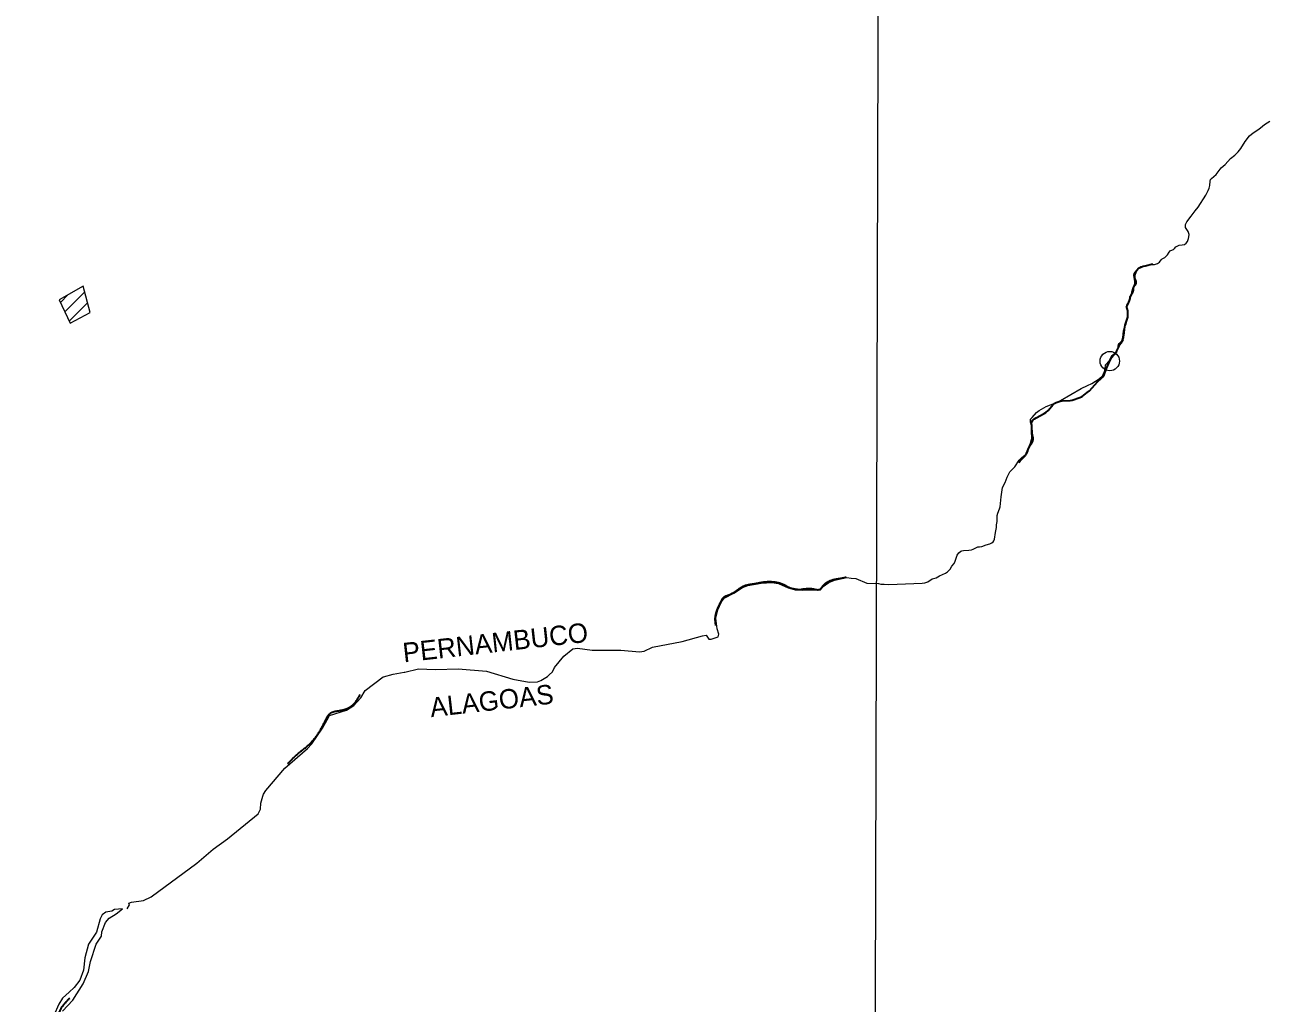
# Model space of a CAD drawing. Extents: x 553962 to 842807, y 8883888 to 9032388.
# Drawn here: x 582130 to 587242, y 8915863 to 8919892 of the extents above; entities that cross this region are included whole.
import ezdxf
from ezdxf.enums import TextEntityAlignment as Align

# ---------------------------------------------------------------- set-up
doc = ezdxf.new("R2010")
doc.units = 0
doc.header["$LTSCALE"] = 160
doc.header["$PDMODE"] = 32
doc.header["$PDSIZE"] = 80
doc.linetypes.add('LONG_DASH_SHORT_DASH', pattern=[9.9, 6, -1.2, 1.5, -1.2])
doc.layers.add('6', color=7, linetype='Continuous', lineweight=13)

msp = doc.modelspace()

# ---------------------------------------------------------------- linework, layer by layer
at = {"layer": '6'}
for p, q in [((582276.5, 8918748), (582308.9, 8918780.4)), ((582294.7, 8918709.6), (582376.4, 8918791.3)), ((582312.9, 8918671.2), (582388.6, 8918746.9))]:
    msp.add_line(p, q, dxfattribs=at)
at = {"layer": '6', "linetype": 'LONG_DASH_SHORT_DASH', "lineweight": 35}
msp.add_line((585799, 8917597.9), (585799.3, 8917597.8), dxfattribs=at)
at = {"layer": '6'}
for points in [[(585656.3, 8924738.8), (585614.8, 8909969.8), (585579.9, 8898162.7)], [(586916.9, 8918999.4), (586921.8, 8919011.7), (586923.2, 8919017.8), (586923.8, 8919027.8), (586919.9, 8919040.7), (586909.9, 8919057.1), (586909, 8919064.2), (586909.4, 8919069.7), (586914.4, 8919080.4), (586932.4, 8919104.2), (586949.8, 8919125.1), (586961.5, 8919140.2), (586992.8, 8919190.2), (587002.7, 8919209.4), (587006.2, 8919218.4), (587008.9, 8919230.4), (587010.4, 8919247.4), (587012.9, 8919254.6), (587016, 8919258.6), (587035, 8919274.8), (587055.6, 8919302.4), (587072, 8919316.4), (587094, 8919340.4), (587112.3, 8919355.2), (587126.1, 8919368.8), (587137.1, 8919382), (587155.1, 8919411), (587172.6, 8919433.8), (587187.4, 8919446.2), (587211.4, 8919462), (587226.2, 8919474.8), (587234.8, 8919481.4), (587256, 8919495)], [(586679.6, 8918760.5), (586680.3, 8918772.5), (586692.5, 8918786.5), (586696.8, 8918798.9), (586696.9, 8918809.3), (586697.7, 8918812.7), (586699.3, 8918815.3), (586704.2, 8918820.1), (586707.7, 8918826.9), (586707.4, 8918834.5), (586702.6, 8918847.7), (586701.8, 8918857.5), (586703.1, 8918864.1), (586709.7, 8918881.3), (586721, 8918893.5), (586725.9, 8918895.7), (586766.1, 8918904.9), (586782.2, 8918905.1), (586794.3, 8918909.1), (586801.8, 8918914.7), (586808.8, 8918923.3), (586813, 8918927.3), (586824.3, 8918933.9), (586830.1, 8918938.5), (586834.8, 8918944.1), (586841.9, 8918955.9), (586845.8, 8918960.3), (586848.8, 8918962.4), (586859.7, 8918966.8), (586863.7, 8918970.4), (586869.3, 8918977.4), (586877.2, 8918981.7), (586883.6, 8918984.1), (586895.7, 8918985.2), (586905.7, 8918987.4), (586911.9, 8918992.7), (586916.9, 8918999.4)], [(586136.8, 8917879.9), (586143.9, 8917898.3), (586146.5, 8917907.1), (586150.7, 8917947.5), (586156.3, 8917986.5), (586166.2, 8918006.3), (586175.4, 8918028.7), (586186.6, 8918050.1), (586197.8, 8918063.5), (586206.1, 8918071.9), (586225, 8918098.7), (586234.8, 8918109.9), (586249.5, 8918120.5), (586256.8, 8918127.7), (586261.3, 8918135.7), (586262.8, 8918149.5), (586276.3, 8918165.5), (586281.8, 8918176.7), (586282.8, 8918182.3), (586282.8, 8918191.1), (586279.2, 8918209.5), (586279.1, 8918219.3), (586275.1, 8918241.3), (586270.8, 8918255.1), (586270.6, 8918261.3), (586271.5, 8918267.7), (586278.2, 8918274.1), (586295.8, 8918294.9), (586307.4, 8918303.7), (586335.1, 8918320.1), (586377.8, 8918336.7), (586395.1, 8918344.9), (586480.1, 8918393.5), (586505.7, 8918406.7), (586524.1, 8918414.9), (586554, 8918433.1), (586568.4, 8918447.3), (586570.6, 8918451.1), (586575.7, 8918463.9), (586578.3, 8918475.3), (586579.7, 8918491.9), (586595.5, 8918507.3), (586602.8, 8918522.3), (586607.5, 8918529.5), (586619.7, 8918540.1), (586627.3, 8918548.9), (586630.1, 8918555.5), (586632.3, 8918569.5), (586634.1, 8918575.1), (586636.7, 8918579.5), (586645.9, 8918589.1), (586648.8, 8918594.9), (586650.6, 8918604.3), (586653.5, 8918631.7), (586658.1, 8918644.7), (586665.3, 8918659.3), (586672.6, 8918692.7), (586672.6, 8918710.3), (586671.1, 8918715.7), (586665.9, 8918726.3), (586666, 8918731.5), (586668, 8918736.7), (586678.5, 8918755.1), (586678.5, 8918755.1), (586679.6, 8918760.5)], [(585824.4, 8917592.5), (585835.6, 8917593.5), (585848.5, 8917598.3), (585866.6, 8917609.5), (585883, 8917614.7), (585896.8, 8917622.9), (585921, 8917633.3), (585928.7, 8917638.5), (585940.3, 8917649.7), (585947.5, 8917662.7), (585957.1, 8917673.5), (585961.2, 8917682.5), (585965.9, 8917699.7), (585968.9, 8917706.9), (585976, 8917717.1), (585984.1, 8917723.9), (585988.6, 8917725.7), (585994.5, 8917727.1), (586017.6, 8917728.5), (586028.1, 8917729.9), (586035.3, 8917731.9), (586054, 8917741.3), (586060.6, 8917742.5), (586070, 8917742.7), (586088.9, 8917750.3), (586104.1, 8917754.3), (586112.5, 8917757.7), (586118, 8917762.1), (586120.7, 8917766.5), (586122.9, 8917773.1), (586126.9, 8917800.7), (586130.7, 8917821.1), (586131.4, 8917832.3), (586133.7, 8917846.3), (586134.3, 8917870.5), (586136.8, 8917879.9)], [(585406.5, 8917564.6), (585417.5, 8917578), (585441.3, 8917595.2), (585463.8, 8917604.5), (585514.8, 8917615.6), (585533.1, 8917613.4)], [(585533.1, 8917613.4), (585551.5, 8917611.2), (585597.6, 8917591.8)], [(584946, 8917362.1), (584956.7, 8917362.1), (584984.5, 8917371.3), (584987.1, 8917382.3), (584980.7, 8917404.5), (584974.8, 8917448.6), (584983.7, 8917481.7), (584998.1, 8917514.8), (585010.1, 8917531), (585049.8, 8917550.4), (585085.7, 8917573.9), (585106.9, 8917582), (585162.1, 8917591.8), (585206.3, 8917594.7), (585224.1, 8917592.2)], [(585224.1, 8917592.2), (585233.4, 8917590.9), (585273.5, 8917573.1), (585302.3, 8917565), (585331.2, 8917562.9), (585406.5, 8917564.6)], [(585597.6, 8917591.8), (585645.8, 8917591.3), (585655.1, 8917588.7), (585668.4, 8917587.5), (585687.5, 8917587.3), (585824.4, 8917592.5)], [(584562.5, 8917316.2), (584584.8, 8917316), (584661, 8917309.7), (584679.6, 8917312.2), (584715.2, 8917328.8), (584836.7, 8917352.1), (584920.8, 8917375.9), (584935.7, 8917377.6), (584946, 8917362.1)], [(584289.7, 8917215.3), (584302.2, 8917227.5), (584311.2, 8917245.5), (584349.8, 8917291.8), (584386.3, 8917322.1), (584405.1, 8917324.1), (584466.3, 8917316.9), (584511.8, 8917316.6), (584562.5, 8917316.2)], [(583694.7, 8917225.9), (583751.3, 8917239.9), (583784.8, 8917238.2)], [(583784.8, 8917238.2), (583823, 8917236.2), (583913.9, 8917240), (584030.3, 8917229.4), (584139.1, 8917197.5), (584207.1, 8917184.8), (584241.1, 8917186), (584254.7, 8917190.7), (584281.9, 8917207.8), (584289.7, 8917215.3)], [(583497.2, 8917101.5), (583513.7, 8917119.7), (583530.7, 8917150.3), (583605.6, 8917205.9)], [(583605.6, 8917205.9), (583606.2, 8917206.4), (583647.1, 8917217.9), (583691.7, 8917225.1), (583694.7, 8917225.9)], [(583374.4, 8917029.3), (583384.1, 8917046.7), (583454.1, 8917069.1), (583484.8, 8917087.9), (583497.2, 8917101.5)], [(583110.2, 8916714.5), (583112.9, 8916723.3), (583122.7, 8916738.7), (583200.6, 8916830.8), (583293.7, 8916911.2), (583311.9, 8916931.1), (583355.3, 8916994.9), (583374.4, 8917029.3)], [(583090.8, 8916642.8), (583100.4, 8916661.6), (583101.2, 8916686.4), (583110.2, 8916714.5)], [(582550.9, 8916251), (582561.6, 8916267.1), (582557.7, 8916274.2), (582569.7, 8916279), (582618.1, 8916284.9), (582650.7, 8916300), (582838.2, 8916439.2), (582906.1, 8916497.3), (582963.8, 8916539.2), (583090.8, 8916642.8)], [(582285.5, 8915829.1), (582327.1, 8915874.5), (582370.1, 8915942.2), (582370.1, 8915942.2), (582392.5, 8915993.1), (582400.2, 8916033.9), (582424, 8916105.2), (582445.6, 8916138.3), (582446.5, 8916156.7), (582461.8, 8916195.3), (582477.1, 8916212.2), (582506.6, 8916230.2), (582531.5, 8916251.2), (582531.5, 8916251.2)], [(582531.5, 8916251.2), (582499.6, 8916248.9), (582488.1, 8916242), (582463.5, 8916237.3), (582448.2, 8916226.2), (582440.5, 8916210.5), (582424.4, 8916155.5), (582392.5, 8916105.1), (582376.8, 8916049.2), (582370.9, 8915998.2), (582356, 8915957.4), (582333.5, 8915927.2), (582311.8, 8915907.8)], [(582311.8, 8915907.8), (582284.6, 8915883.4), (582269.3, 8915857.9), (582249.3, 8915811.2), (582221.8, 8915774.3), (582196.3, 8915750.1), (582178.4, 8915720.3), (582168.2, 8915682.9), (582167.8, 8915629.8), (582154.6, 8915606.4), (582129.9, 8915587.7)]]:
    msp.add_lwpolyline(points, dxfattribs=at)
at = {"layer": '6', "linetype": 'LONG_DASH_SHORT_DASH', "lineweight": 35}
for points in [[(586698.2, 8918860.5), (586699.5, 8918868.4), (586701.6, 8918872.3), (586709.1, 8918881.7), (586716.2, 8918889), (586725.8, 8918894.1), (586735.2, 8918897.5), (586743.7, 8918899.7), (586775.5, 8918907)], [(586597.6, 8918506.7), (586605.9, 8918523.4), (586611.9, 8918529.9), (586617.3, 8918534), (586622.3, 8918538.9), (586623.4, 8918540.9), (586626.4, 8918548.8), (586631.3, 8918557.1), (586634.3, 8918565.1), (586637.8, 8918573), (586643.9, 8918581.7), (586648.8, 8918589.4), (586652.3, 8918595.6), (586654.7, 8918605.5), (586654.8, 8918613.8), (586656.7, 8918622.1), (586657.8, 8918638.2), (586659.7, 8918646.3), (586661, 8918654.2), (586663.5, 8918662.4), (586666.6, 8918670.9), (586668.9, 8918678.8), (586672.1, 8918687.1), (586672.3, 8918702.8), (586672, 8918712), (586671, 8918719.4), (586667.1, 8918727.6), (586666.9, 8918728.6), (586672.8, 8918742), (586679.1, 8918756), (586680.9, 8918764.7), (586683.4, 8918772.6), (586688.5, 8918781.8), (586690.3, 8918790.4), (586695.8, 8918807.9), (586701.3, 8918821.4), (586701.6, 8918825.4), (586701.4, 8918834.4), (586699.1, 8918851.1), (586698.2, 8918860.5)], [(586513.5, 8918384.7), (586547.2, 8918421.3), (586562.5, 8918435.2), (586568.8, 8918442), (586573.9, 8918450.3), (586577.2, 8918457.8), (586580, 8918465.9), (586583.2, 8918474), (586594.1, 8918498), (586597.6, 8918506.7)], [(586222.6, 8918087.9), (586223.9, 8918090.1), (586228.4, 8918096.1), (586236.5, 8918103.6), (586243.8, 8918110.9), (586250.2, 8918118.5), (586254.6, 8918126.4), (586260.8, 8918142.7), (586268.8, 8918158.2), (586272.8, 8918166.7), (586277.2, 8918183.1), (586278.1, 8918191.2), (586277.5, 8918199.5), (586276, 8918207.8), (586276, 8918223.7), (586276.6, 8918240), (586275.8, 8918254), (586276.7, 8918256.6), (586280.2, 8918263.9), (586287.4, 8918268.9), (586293.9, 8918272.7), (586327.8, 8918291.2), (586334.7, 8918295.4), (586343.5, 8918302.7), (586357.8, 8918319.5), (586363.1, 8918326.4), (586369.2, 8918332), (586377.3, 8918336.3), (586385.6, 8918339.6), (586393.6, 8918341.5), (586401.5, 8918342.9), (586433.8, 8918344.2), (586442.3, 8918345.8), (586450.6, 8918348.2), (586466.5, 8918353.8), (586474.8, 8918357.3), (586483.3, 8918361.6), (586490.3, 8918366.2), (586504.2, 8918377.5), (586513.5, 8918384.7)]]:
    msp.add_lwpolyline(points, dxfattribs=at)
at = {"layer": '6'}
msp.add_lwpolyline([(582271.3, 8918759), (582316.7, 8918663.1), (582399.6, 8918706.8), (582369.9, 8918815)], close=True, dxfattribs=at)
at = {"layer": '6', "linetype": 'LONG_DASH_SHORT_DASH', "lineweight": 35}
for points in [[(584975.9, 8917417.5), (584975.5, 8917419.7), (584973.4, 8917450.5), (584981.3, 8917482.8), (584997.8, 8917518.6), (585007.8, 8917534.4), (585031.4, 8917545.1), (585065.1, 8917565.2), (585093, 8917581.7), (585131, 8917589.6), (585175.4, 8917597.4), (585208.4, 8917598.2), (585232.7, 8917594.6), (585252.1, 8917588.1), (585282.1, 8917573.1), (585320.8, 8917565.9)], [(585320.8, 8917565.9), (585379.6, 8917568.1), (585403.9, 8917567.3), (585406.1, 8917568.8), (585417.5, 8917582.4), (585451.2, 8917604.6), (585489.2, 8917612.5), (585512.1, 8917617.4)], [(583212.7, 8916848.6), (583254.2, 8916889.7), (583303.2, 8916930.2), (583370.6, 8917031.5), (583385.8, 8917055.2), (583431.4, 8917068.7), (583482, 8917092.3), (583511.3, 8917134.2)], [(582166.9, 8915321.8), (582167.5, 8915329.8), (582184.4, 8915456.4), (582181, 8915596.5), (582191.1, 8915684.3), (582204.6, 8915733.2), (582245.1, 8915780.5), (582285.6, 8915849.7), (582314.9, 8915883.4)]]:
    msp.add_spline(points, degree=3, dxfattribs=at)
at = {"layer": '6'}
msp.add_point((586597.6, 8918506.7), dxfattribs=at)

# ---------------------------------------------------------------- texts
for s, p in [('PERNAMBUCO', (584071.7, 8917308.3)), ('ALAGOAS', (584056.6, 8917068.5))]:
    msp.add_text(s, height=80, rotation=6.379, dxfattribs=at).set_placement(p, align=Align.CENTER)

doc.saveas('drawing.dxf')
